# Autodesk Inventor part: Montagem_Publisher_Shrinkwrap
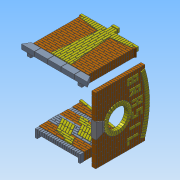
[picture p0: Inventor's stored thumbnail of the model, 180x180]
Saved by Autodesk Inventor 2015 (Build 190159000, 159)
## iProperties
Created: 2015-04
Part Number: Montagem_Publisher_Shrinkwrap
Material: Generic
Document SubType Name: Modeling
Designer: Paulo Kazuo Inoue
Density: 1 g/cm^3
Appearance: Default
Author: Paulo Kazuo Inoue
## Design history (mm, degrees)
derived "Montagem_Publisher.iam"
body "Solid1"
node "Modulo 1.ipt:1"
node "Modulo 2.ipt:1"
body "Solid2"
node "Modulo 3.ipt:1"
body "Solid3"
